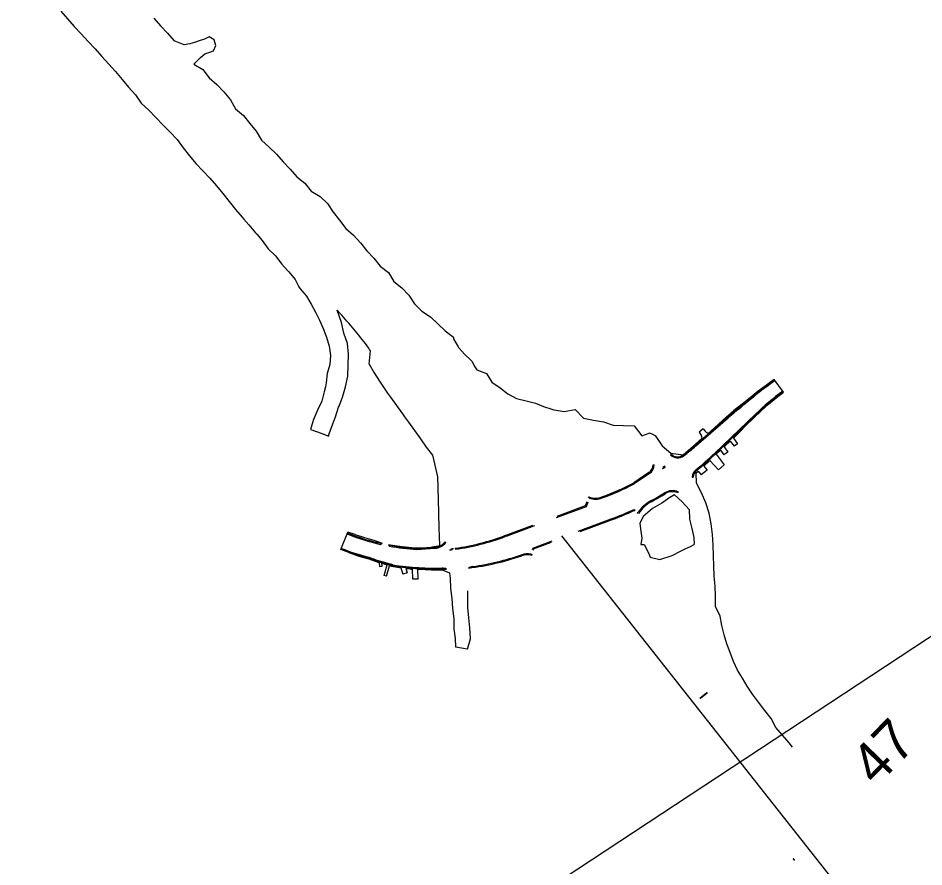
# Model space of a CAD drawing. Extents: x -5665 to 1997148, y 4 to 812485.
# Drawn here: x 1961620 to 1966066, y 802882 to 807051 of the extents above; entities that cross this region are included whole.
import ezdxf

# ---------------------------------------------------------------- set-up
doc = ezdxf.new("R2010")
doc.units = 0
for name, color, linetype in [('RD_EX_H20_TX', 7, 'Continuous'), ('RD_EX_Pavement_Markings', 7, 'Continuous'), ('RD_EX_UT', 7, 'Continuous'), ('RD_PD_CstnLmt', 7, 'Continuous'), ('RD_PD_SW', 7, 'Continuous'), ('RD_SHT_TX', 7, 'Continuous')]:
    doc.layers.add(name, color=color, linetype=linetype)

msp = doc.modelspace()

# ---------------------------------------------------------------- linework, layer by layer
at = {"layer": 'RD_EX_H20_TX'}
msp.add_lwpolyline([(1962404, 800141.4), (1962156.8, 800249.1), (1961619.9, 801061.9), (1967047, 804639.1), (1967746.1, 803578.5), (1967695.1, 802969), (1968000.2, 801689.9), (1968522.9, 801587.9), (1968575.1, 801281.2), (1968568.4, 800839.6), (1968542.7, 800594.7), (1964601.3, 797996.7), (1963740.9, 798826.2)], close=True, dxfattribs=at)
at = {"layer": 'RD_EX_Pavement_Markings'}
msp.add_line((1964286.7, 804508.1), (1966609.3, 801563.1), dxfattribs=at)
at = {"layer": 'RD_EX_UT'}
for p, q in [((1964966.2, 803710.7), (1965000, 803738.1)), ((1965002.4, 803735.3), (1964968.6, 803707.9))]:
    msp.add_line(p, q, dxfattribs=at)
for points in [[(1964999.7, 803735.1), (1965000.2, 803735), (1965000.8, 803735.1), (1965001.1, 803735.6), (1965001.2, 803736.1), (1965001, 803736.6), (1965000.5, 803737), (1965000, 803737), (1964999.5, 803736.7), (1964999.2, 803736.2), (1964999.3, 803735.7), (1964999.6, 803735.2), (1964999.7, 803735.1)], [(1964999.8, 803735.3), (1965000.3, 803735.2), (1965000.7, 803735.4), (1965001, 803735.8), (1965001, 803736.3), (1965000.6, 803736.7), (1965000.2, 803736.8), (1964999.7, 803736.6), (1964999.4, 803736.2), (1964999.5, 803735.7), (1964999.8, 803735.3)], [(1964999.9, 803735.5), (1965000.3, 803735.4), (1965000.7, 803735.6), (1965000.8, 803736), (1965000.6, 803736.4), (1965000.3, 803736.6), (1964999.8, 803736.5), (1964999.6, 803736.1), (1964999.7, 803735.7), (1964999.9, 803735.5)], [(1965000, 803735.7), (1965000.3, 803735.6), (1965000.6, 803735.9), (1965000.6, 803736.2), (1965000.3, 803736.4), (1964999.9, 803736.3), (1964999.8, 803736), (1965000, 803735.7), (1965000, 803735.7)], [(1965000.1, 803735.8), (1965000.3, 803735.8), (1965000.4, 803736.1), (1965000.2, 803736.2), (1965000, 803736), (1965000.1, 803735.8)], [(1965425.1, 802919.4), (1965425.7, 802919.2), (1965426.2, 802919.4), (1965426.6, 802919.8), (1965426.7, 802920.3), (1965426.5, 802920.8), (1965426.1, 802921.2), (1965425.5, 802921.2), (1965425, 802921), (1965424.7, 802920.5), (1965424.7, 802919.9), (1965425.1, 802919.5), (1965425.1, 802919.4)], [(1965425.1, 802919.4), (1965425.7, 802919.2), (1965426.2, 802919.4), (1965426.6, 802919.8), (1965426.7, 802920.3), (1965426.5, 802920.8), (1965426.1, 802921.2), (1965425.5, 802921.2), (1965425, 802921), (1965424.7, 802920.5), (1965424.7, 802919.9), (1965425.1, 802919.5), (1965425.1, 802919.4)], [(1965425.3, 802919.6), (1965425.7, 802919.4), (1965426.2, 802919.6), (1965426.5, 802920), (1965426.5, 802920.5), (1965426.2, 802920.9), (1965425.7, 802921), (1965425.2, 802920.9), (1965424.9, 802920.5), (1965424.9, 802920), (1965425.3, 802919.6)], [(1965425.3, 802919.6), (1965425.7, 802919.4), (1965426.2, 802919.6), (1965426.5, 802920), (1965426.5, 802920.5), (1965426.2, 802920.9), (1965425.7, 802921), (1965425.2, 802920.9), (1965424.9, 802920.5), (1965424.9, 802920), (1965425.3, 802919.6)], [(1965425.4, 802919.7), (1965425.8, 802919.6), (1965426.2, 802919.8), (1965426.3, 802920.2), (1965426.2, 802920.6), (1965425.8, 802920.8), (1965425.3, 802920.7), (1965425.1, 802920.4), (1965425.2, 802919.9), (1965425.4, 802919.7)], [(1965425.4, 802919.7), (1965425.8, 802919.6), (1965426.2, 802919.8), (1965426.3, 802920.2), (1965426.2, 802920.6), (1965425.8, 802920.8), (1965425.3, 802920.7), (1965425.1, 802920.4), (1965425.2, 802919.9), (1965425.4, 802919.7)], [(1965425.5, 802919.9), (1965425.8, 802919.8), (1965426.1, 802920.1), (1965426.1, 802920.4), (1965425.8, 802920.6), (1965425.4, 802920.5), (1965425.3, 802920.2), (1965425.5, 802919.9), (1965425.5, 802919.9)], [(1965425.5, 802919.9), (1965425.8, 802919.8), (1965426.1, 802920.1), (1965426.1, 802920.4), (1965425.8, 802920.6), (1965425.4, 802920.5), (1965425.3, 802920.2), (1965425.5, 802919.9), (1965425.5, 802919.9)], [(1965425.6, 802920.1), (1965425.8, 802920.1), (1965425.9, 802920.3), (1965425.7, 802920.4), (1965425.5, 802920.3), (1965425.6, 802920.1)], [(1965425.6, 802920.1), (1965425.8, 802920.1), (1965425.9, 802920.3), (1965425.7, 802920.4), (1965425.5, 802920.3), (1965425.6, 802920.1)], [(1965428.3, 802915.6), (1965428.8, 802915.4), (1965429.4, 802915.6), (1965429.8, 802916), (1965429.9, 802916.5), (1965429.7, 802917), (1965429.2, 802917.4), (1965428.7, 802917.4), (1965428.2, 802917.2), (1965427.9, 802916.7), (1965427.9, 802916.1), (1965428.2, 802915.6), (1965428.3, 802915.6)], [(1965428.3, 802915.6), (1965428.8, 802915.4), (1965429.4, 802915.6), (1965429.8, 802916), (1965429.9, 802916.5), (1965429.7, 802917), (1965429.2, 802917.4), (1965428.7, 802917.4), (1965428.2, 802917.2), (1965427.9, 802916.7), (1965427.9, 802916.1), (1965428.2, 802915.6), (1965428.3, 802915.6)], [(1965428.4, 802915.8), (1965428.9, 802915.6), (1965429.4, 802915.8), (1965429.6, 802916.2), (1965429.6, 802916.7), (1965429.3, 802917.1), (1965428.8, 802917.2), (1965428.4, 802917.1), (1965428.1, 802916.6), (1965428.1, 802916.1), (1965428.4, 802915.8)], [(1965428.4, 802915.8), (1965428.9, 802915.6), (1965429.4, 802915.8), (1965429.6, 802916.2), (1965429.6, 802916.7), (1965429.3, 802917.1), (1965428.8, 802917.2), (1965428.4, 802917.1), (1965428.1, 802916.6), (1965428.1, 802916.1), (1965428.4, 802915.8)], [(1965428.5, 802915.9), (1965429, 802915.8), (1965429.3, 802916), (1965429.5, 802916.4), (1965429.3, 802916.8), (1965428.9, 802917), (1965428.5, 802916.9), (1965428.3, 802916.6), (1965428.3, 802916.1), (1965428.5, 802915.9)], [(1965428.5, 802915.9), (1965429, 802915.8), (1965429.3, 802916), (1965429.5, 802916.4), (1965429.3, 802916.8), (1965428.9, 802917), (1965428.5, 802916.9), (1965428.3, 802916.6), (1965428.3, 802916.1), (1965428.5, 802915.9)], [(1965428.6, 802916.1), (1965429, 802916), (1965429.2, 802916.3), (1965429.2, 802916.6), (1965428.9, 802916.8), (1965428.6, 802916.7), (1965428.5, 802916.4), (1965428.6, 802916.1), (1965428.6, 802916.1)], [(1965428.6, 802916.1), (1965429, 802916), (1965429.2, 802916.3), (1965429.2, 802916.6), (1965428.9, 802916.8), (1965428.6, 802916.7), (1965428.5, 802916.4), (1965428.6, 802916.1), (1965428.6, 802916.1)], [(1965428.8, 802916.3), (1965429, 802916.3), (1965429.1, 802916.5), (1965428.9, 802916.6), (1965428.7, 802916.5), (1965428.8, 802916.3)], [(1965428.8, 802916.3), (1965429, 802916.3), (1965429.1, 802916.5), (1965428.9, 802916.6), (1965428.7, 802916.5), (1965428.8, 802916.3)]]:
    msp.add_lwpolyline(points, dxfattribs=at)
at = {"layer": 'RD_PD_CstnLmt'}
for p, q in [((1963199.4, 805601.5), (1963186.1, 805616.2)), ((1963342.6, 805350.3), (1963349.6, 805416.2)), ((1965095.2, 805090.2), (1965133, 805123.9)), ((1965058.2, 805056.4), (1965095.2, 805090.2)), ((1964981.6, 805033.9), (1964962.9, 805017)), ((1964962.9, 805017), (1964973.4, 804999.3)), ((1964981.6, 805033.9), (1964991.7, 805021.6)), ((1965007.8, 805012.6), (1965021.1, 805023)), ((1965021.1, 805023), (1965058.2, 805056.4)), ((1964745.4, 805000.5), (1964746.8, 804999.9)), ((1964945.4, 804957.6), (1964976.9, 804987.8)), ((1965115.5, 804972.6), (1965134, 804947.9)), ((1965130.6, 804986.9), (1965150.6, 804960.3)), ((1964883.5, 804906), (1964908.6, 804926)), ((1964908.6, 804926), (1964945.4, 804957.6)), ((1965066.6, 804928.3), (1965083.9, 804905.2)), ((1965085.6, 804945.1), (1965102.8, 804919.3)), ((1965150.6, 804960.3), (1965134, 804947.9)), ((1965045.5, 804908.8), (1965051.3, 804914.8)), ((1965045.5, 804908.8), (1965084.7, 804855.6)), ((1965102.8, 804919.3), (1965083.9, 804905.2)), ((1964984.8, 804849.7), (1965015.7, 804877.6)), ((1964984.8, 804849.7), (1965001.2, 804830.1)), ((1965015.7, 804877.6), (1965057.6, 804831.2)), ((1965057.6, 804831.2), (1965084.7, 804855.6)), ((1964948.5, 804817), (1964957.6, 804825.2)), ((1964957.6, 804825.2), (1964973.1, 804806.7)), ((1965001.2, 804830.1), (1964973.1, 804806.7)), ((1963204.3, 804440.1), (1963238.4, 804526)), ((1963274.8, 804513.8), (1963238.4, 804526)), ((1963274.8, 804513.8), (1963320.2, 804499.7)), ((1963320.2, 804499.7), (1963365.9, 804486.4)), ((1963365.9, 804486.4), (1963406.6, 804472.3)), ((1963243.2, 804425.4), (1963204.3, 804440.1)), ((1963437.9, 804465.4), (1963458, 804461.4)), ((1963458, 804461.4), (1963505.2, 804454.5)), ((1963505.2, 804454.5), (1963552.8, 804449.8)), ((1963552.8, 804449.8), (1963600.5, 804449.4)), ((1963600.5, 804449.4), (1963648.1, 804452.4)), ((1963682.7, 804456.3), (1963648.1, 804452.4)), ((1963243.2, 804425.4), (1963292.1, 804408.5)), ((1963292.1, 804408.5), (1963341.8, 804394.5)), ((1963341.8, 804394.5), (1963390.9, 804376.8)), ((1963390.9, 804376.8), (1963391.9, 804376.5)), ((1963404.9, 804356.5), (1963392.9, 804355.7)), ((1963403.4, 804372.9), (1963430.9, 804364.5)), ((1963416.7, 804312.2), (1963430.9, 804364.5)), ((1963428.2, 804309.1), (1963442.5, 804361.1)), ((1963442.5, 804361.1), (1963492.3, 804351.8)), ((1963498.6, 804351), (1963507.7, 804319.3)), ((1963522.4, 804347.8), (1963544.2, 804344.8)), ((1963522.4, 804347.8), (1963528.9, 804325.4)), ((1963428.2, 804309.1), (1963416.7, 804312.2)), ((1963528.9, 804325.4), (1963507.7, 804319.3)), ((1963557.9, 804294.2), (1963555.1, 804344.5)), ((1963583.8, 804295.6), (1963581.2, 804343.8)), ((1963586.5, 804343.7), (1963648.8, 804340.2)), ((1963648.8, 804340.2), (1963701.2, 804340.2)), ((1963701.2, 804340.2), (1963736.9, 804325.2)), ((1963583.8, 804295.6), (1963557.9, 804294.2))]:
    msp.add_line(p, q, dxfattribs=at)
for points in [[(1961829.4, 807084.3), (1961862.1, 807046.5), (1961895.3, 807009.1), (1961930, 806973.1), (1961963.4, 806935.8), (1961997.5, 806899.3), (1962030.4, 806861.6), (1962064.4, 806825), (1962097.9, 806787.9), (1962130.1, 806749.5), (1962162.4, 806711.3), (1962195.9, 806674.2), (1962224.5, 806632.6), (1962261.7, 806598.9), (1962296.2, 806562.7), (1962330.1, 806525.9), (1962365.8, 806490.8), (1962400.7, 806454.9), (1962429.2, 806413.3), (1962460.8, 806374.5), (1962492.9, 806336.5), (1962526.3, 806299.9), (1962560.1, 806263.6), (1962593.7, 806227.1), (1962625.1, 806188.7), (1962655.9, 806149.8), (1962687.2, 806110.7), (1962719.9, 806072.9), (1962728.5, 806062.9), (1962752.3, 806034.7), (1962785, 805996.7), (1962791.4, 805989.3), (1962817.5, 805958.3), (1962846.5, 805916.8), (1962883.3, 805882.7), (1962883.8, 805882.4), (1962915, 805842.7), (1962942.8, 805810.7), (1962945.4, 805807.7), (1962948.1, 805804.8), (1962980.4, 805766.5), (1962997.6, 805730), (1963003.8, 805720.3), (1963015.1, 805708.1), (1963015.1, 805708.1), (1963027.7, 805694.7), (1963034.7, 805685.1), (1963057.5, 805645.9), (1963078.9, 805606.5), (1963099.1, 805566.7), (1963117.6, 805525.7), (1963133.2, 805483.2), (1963146.1, 805439.4), (1963153.1, 805394.2), (1963150.5, 805348.4), (1963137, 805304.2), (1963131.9, 805259.6), (1963128.1, 805240.2), (1963122.5, 805215.6), (1963112.8, 805175.1), (1963111.2, 805169.8), (1963090.1, 805124.3), (1963070.4, 805078.3), (1963058.1, 805041), (1963055.1, 805030.6), (1963066.1, 805026.5), (1963077.4, 805022.4), (1963083, 805020.3), (1963084.9, 805019.6), (1963107.4, 805011.3), (1963118.7, 805007.2), (1963120.6, 805006.5), (1963126.2, 805004.4), (1963137.4, 805000.3), (1963143.6, 804998), (1963147.2, 805008.1), (1963160.2, 805045.2), (1963177, 805092.3), (1963192.8, 805139.7), (1963195.1, 805144.8), (1963211.6, 805188.3), (1963220.4, 805216.8), (1963226.8, 805239.5), (1963237.9, 805292), (1963240, 805345.6), (1963241.8, 805399.2), (1963237.3, 805452.8)], [(1962285.6, 807050.4), (1962318.2, 807013.2), (1962352.5, 806976.8), (1962385.5, 806939.3)], [(1962582.4, 806943.5), (1962557.4, 806958.2), (1962534.1, 806946.4), (1962509.1, 806939.5), (1962484.8, 806930.6), (1962462.2, 806924.7), (1962435.4, 806919.3), (1962385.5, 806939.3)], [(1962514.6, 806857.2), (1962536, 806875), (1962556.6, 806881.7), (1962579.1, 806890.4), (1962590.4, 806916.7), (1962582.4, 806943.5)], [(1962481.8, 806824.1), (1962514.6, 806857.2)], [(1962481.8, 806824.1), (1962527.1, 806797.6), (1962557.4, 806757.6), (1962594.6, 806723.8), (1962630.1, 806688.5), (1962661.7, 806649.7), (1962686.4, 806604.6), (1962725.7, 806572.8), (1962756.4, 806533.1), (1962788.3, 806494.5), (1962814.8, 806451.1), (1962852.1, 806417.4), (1962887.5, 806382), (1962921.5, 806345.3), (1962954.8, 806308.2), (1962987.8, 806271), (1963027.2, 806239.7), (1963058.6, 806201), (1963102.6, 806174.2), (1963138.8, 806139.7), (1963167, 806097.4), (1963197.9, 806057.8), (1963228.3, 806017.6), (1963265.9, 805983.9), (1963300.6, 805947.5), (1963332, 805908.1), (1963365.8, 805870.9), (1963397.4, 805832.1), (1963438.2, 805801.6), (1963463.6, 805757.2), (1963502.6, 805725), (1963537.6, 805689.2), (1963565.5, 805647.1), (1963601.1, 805611.9), (1963644, 805583.3), (1963680.4, 805548.8), (1963716.6, 805514.1), (1963756.4, 805482.7), (1963756.1, 805475.1), (1963779.2, 805435.8), (1963781.5, 805433), (1963812.3, 805398.3), (1963813.5, 805396.8), (1963840.9, 805371.8), (1963840.9, 805371.8), (1963846.5, 805364.9), (1963861.2, 805337.6), (1963872.1, 805323), (1963918.3, 805304.3), (1963945.7, 805262.2), (1963985.2, 805235.1), (1964023.1, 805205), (1964065.9, 805182.9), (1964113, 805170.7), (1964159.4, 805158.9), (1964198.4, 805142.3), (1964198.5, 805142.3), (1964203.3, 805140.7), (1964233.9, 805130.9), (1964250, 805126.5), (1964281.4, 805121.6), (1964299.8, 805118.9), (1964354.2, 805128.3), (1964394.2, 805085.1), (1964443.5, 805075.6), (1964493.1, 805067.7), (1964540.7, 805052), (1964591.8, 805049.3), (1964643.3, 805048), (1964681.6, 804998.9), (1964717.2, 805012.3)], [(1963237.3, 805452.8), (1963218.6, 805503.6), (1963206.9, 805555.5), (1963186.1, 805616.2)], [(1963342.6, 805350.3), (1963367.2, 805308.6), (1963392.9, 805267.8), (1963419.6, 805227.6), (1963433.2, 805208.2), (1963448, 805188.3), (1963477, 805147.5), (1963506.5, 805106.9), (1963516.8, 805092.3), (1963535.9, 805066.2), (1963565.5, 805025.7), (1963594.1, 804984.5), (1963623.4, 804943.8)], [(1965130.6, 804986.9), (1965161.1, 805017), (1965194.9, 805053), (1965230.2, 805087.5), (1965266.1, 805121.3), (1965302.9, 805154.1), (1965340.9, 805185.5), (1965376.8, 805212.5), (1965330.5, 805275.6), (1965293.6, 805247.9), (1965252.6, 805218), (1965213.2, 805186.1), (1965174.1, 805153.9), (1965133, 805123.9)], [(1964746.8, 804999.9), (1964781.3, 804949.6), (1964823.6, 804913.3), (1964883.5, 804906)], [(1965085.6, 804945.1), (1965088.8, 804947.9), (1965115.5, 804972.6)], [(1963623.4, 804943.8), (1963654.4, 804904), (1963678.5, 804797.5), (1963681.5, 804688.2), (1963685.3, 804547.2), (1963687.6, 804461.5), (1963682.7, 804456.3)], [(1965051.3, 804914.8), (1965066.6, 804928.3)], [(1965224.5, 803730), (1965197.9, 803769), (1965174.7, 803809.3), (1965150, 803848.5), (1965131.6, 803891), (1965114.1, 803933.9), (1965097.9, 803977.3), (1965084.8, 804021.9), (1965073.5, 804067.1), (1965065.3, 804113.2), (1965043.4, 804160.3), (1965043.1, 804210.4), (1965040.7, 804260.4), (1965036.6, 804310.2), (1965034.2, 804360.1), (1965032.4, 804410.1), (1965031.1, 804461.4), (1965028, 804514), (1965021.9, 804566.7), (1965011.4, 804618.9), (1964995.7, 804670), (1964974.1, 804718.8), (1964950.2, 804766.5), (1964948.5, 804817)], [(1964823.8, 804698.7), (1964839.3, 804710), (1964878.9, 804673.9), (1964912.7, 804637.7), (1964915.3, 804589.1), (1964927.1, 804544.3), (1964935.8, 804498.9), (1964938.5, 804464.6)], [(1964823.8, 804698.7), (1964779.9, 804668.8), (1964734.1, 804641.8)], [(1964734.1, 804641.8), (1964687.6, 804602.8), (1964687.4, 804602.3), (1964671.4, 804568.6), (1964676.6, 804530.7), (1964681.1, 804496.6), (1964675.8, 804465.4), (1964675.8, 804465.4), (1964693, 804464.8), (1964713.2, 804424.9), (1964721.7, 804403.1)], [(1964721.7, 804403.1), (1964770.2, 804392.2), (1964829.7, 804411.5), (1964874.4, 804434), (1964894.5, 804443.8), (1964908.2, 804450), (1964919.6, 804455.4), (1964938.5, 804464.6)], [(1963391.9, 804376.5), (1963392.9, 804355.7)], [(1963403.4, 804372.9), (1963404.9, 804356.5)], [(1963492.3, 804351.8), (1963496, 804351.3), (1963498.6, 804351)], [(1963544.2, 804344.8), (1963548.7, 804344.7), (1963555.1, 804344.5)], [(1963581.2, 804343.8), (1963586.5, 804343.7)], [(1963736.9, 804325.2), (1963740.5, 804299.5), (1963742.5, 804249.6), (1963748.8, 804199.9), (1963752.4, 804150), (1963758.6, 804100.3), (1963758.6, 804050.2), (1963765.3, 804003.7), (1963766.2, 803962.4), (1963766.9, 803962.3), (1963768.3, 803962), (1963795.9, 803957), (1963823.4, 803951.9), (1963824.9, 803951.6), (1963824.9, 803951.6), (1963840.2, 804002.5), (1963836.6, 804055.8), (1963832.4, 804105.6), (1963827.7, 804155.4), (1963826.7, 804205.5), (1963826.4, 804237.5)], [(1965420.7, 803468.9), (1965404.9, 803490.3), (1965372.2, 803528.1), (1965339, 803565.6), (1965315.4, 803610.7), (1965284.5, 803650), (1965254.4, 803689.9), (1965224.5, 803730)]]:
    msp.add_lwpolyline(points, dxfattribs=at)
for centre, radius, start, end in [((1961373.6, 803949.9), 2462, 37.2891, 42.1319), ((1961309.9, 804040.1), 2460.5, 34.0056, 34.7351), ((1965011, 805037.4), 25, 219.3511, 262.6705), ((1964597.5, 804688.2), 345.5, 64.6623, 69.7279), ((1964952, 804986.5), 25, 3.0273, 30.8982)]:
    msp.add_arc(centre, radius, start, end, dxfattribs=at)
at = {"layer": 'RD_PD_SW'}
for p, q in [((1965331.3, 805274.5), (1965334.2, 805270.5)), ((1965375.6, 805214.1), (1965372.7, 805218.1)), ((1965039.5, 804914.4), (1965238.8, 805105.6)), ((1964944.7, 804954.5), (1965102.3, 805090.4)), ((1964946.7, 804949.6), (1965105.6, 805086.7)), ((1965043, 804910.8), (1965242.2, 805102)), ((1964822.5, 804905.1), (1964826.1, 804908.6)), ((1964736.5, 804855.8), (1964741.5, 804855.8)), ((1964788.2, 804841.8), (1964790.9, 804838)), ((1964792.4, 804844.7), (1964794.8, 804841.2)), ((1964715.7, 804818.3), (1964641.3, 804767.3)), ((1964718.6, 804814.2), (1964643.9, 804763)), ((1964928.4, 804796.3), (1964933.4, 804796.1)), ((1964860.2, 804723.6), (1964858.2, 804719)), ((1964405.2, 804656.1), (1964412.9, 804677)), ((1964409.1, 804652.2), (1964417.6, 804675.4)), ((1964420.8, 804698.6), (1964418.4, 804692)), ((1964423.8, 804692.3), (1964423.1, 804690.4)), ((1964263.1, 804598), (1964409.1, 804652.2)), ((1964266.3, 804604.5), (1964405.2, 804656.1)), ((1964642.1, 804631.8), (1964645.4, 804629.6)), ((1964642.5, 804637.5), (1964648.2, 804633.8)), ((1964664.7, 804617.1), (1964658.8, 804620.9)), ((1964663.3, 804624), (1964661.6, 804625.1)), ((1964368.3, 804530.4), (1964531.1, 804590.9)), ((1964377.9, 804528.6), (1964532.8, 804586.2)), ((1964023.4, 804514.2), (1964145.6, 804559.6)), ((1964025.1, 804509.5), (1964156, 804558.2)), ((1963236.5, 804521.3), (1963234.7, 804516.6)), ((1964146.1, 804447.8), (1964240.3, 804482.8)), ((1963206.6, 804446), (1963204.8, 804441.4)), ((1963575.3, 804445.7), (1963665.4, 804451.4)), ((1963575.4, 804440.6), (1963665.7, 804446.4)), ((1963715.2, 804478.1), (1963719.1, 804475.1)), ((1963753.5, 804447), (1963753.9, 804442)), ((1963765.6, 804446.8), (1963765.9, 804441.8)), ((1964146.1, 804447.8), (1964143.5, 804438.5)), ((1964150.2, 804444), (1964148.3, 804437.3)), ((1964150.2, 804444), (1964238.3, 804476.7)), ((1964137.5, 804417.3), (1964138.1, 804419.2)), ((1964141, 804411.2), (1964142.9, 804418))]:
    msp.add_line(p, q, dxfattribs=at)
for centre, radius, start, end in [((1967047.5, 802933.9), 2902.4, 126.2503, 130.4535), ((1967047.5, 802933.9), 2897.4, 126.2503, 130.4551), ((1966156.8, 804148.8), 1326, 126.2503, 133.812), ((1966156.8, 804148.8), 1321, 126.2503, 133.812), ((1966999.3, 802891.6), 2904, 129.188, 130.7851), ((1966999.3, 802891.6), 2899, 129.1864, 130.7851), ((1964037.9, 806004.3), 1387.3, 307.543, 310.8192), ((1964037.9, 806004.3), 1392.3, 307.543, 310.751), ((1964857, 804938.5), 48, 223.9559, 307.543), ((1964857, 804938.5), 43, 223.9559, 307.543), ((1964013.2, 805984.2), 1482.4, 308.9999, 313.812), ((1964013.2, 805984.2), 1487.4, 308.9999, 313.812), ((1964688.6, 804857.9), 48, 304.4417, 357.4456), ((1964688.6, 804857.9), 53, 304.4417, 357.7496), ((1964013.2, 805984.2), 1380.4, 303.851, 304.1545), ((1964013.2, 805984.2), 1375.4, 304.1271, 304.5601), ((1964013.2, 805984.2), 1380.4, 304.362, 304.5961), ((1964976.4, 804794.8), 48, 128.9999, 178.2847), ((1964976.4, 804794.8), 43, 128.9999, 178.2847), ((1964013.2, 805984.2), 1369.4, 290.1469, 297.2985), ((1964013.2, 805984.2), 1374.4, 290.1469, 297.3115), ((1964013.2, 805984.2), 1486.4, 298.5815, 301.6403), ((1964013.2, 805984.2), 1491.4, 298.5815, 301.6403), ((1964831.3, 804656.6), 73, 66.7023, 121.6403), ((1964831.3, 804656.6), 68, 66.7023, 121.6403), ((1964452.9, 804785.9), 93, 249.8307, 290.1469), ((1964452.9, 804785.9), 98, 252.7523, 290.1469), ((1964809.7, 804522.7), 178, 118.5884, 145.3211), ((1964809.7, 804522.7), 173, 118.5884, 146.9307), ((1964013.2, 805984.2), 1486.4, 290.3874, 295.0451), ((1964013.2, 805984.2), 1491.4, 290.3874, 294.9383), ((1963642, 805540.6), 1101.9, 248.3103, 257.2657), ((1963642, 805540.6), 1096.9, 248.3103, 257.5395), ((1963616.7, 805536.3), 1099.6, 277.7805, 290.8813), ((1963616.7, 805536.3), 1104.6, 277.7639, 290.873), ((1963642, 805540.6), 1094.9, 289.5662, 290.3874), ((1963642, 805540.6), 1099.9, 289.5662, 290.3874), ((1963642, 805540.6), 1182.9, 248.3103, 255.03), ((1963642, 805540.6), 1177.9, 248.3103, 255.0414), ((1963394.7, 804480.1), 15, 286.9953, 314.9755), ((1963452, 804468.4), 15, 202.1143, 230.2794), ((1963642, 805540.6), 1096.9, 259.2915, 266.519), ((1963642, 805540.6), 1101.9, 259.5687, 266.5353), ((1963661.1, 804519.3), 68, 273.6667, 322.7034), ((1963661.1, 804519.3), 73, 273.6667, 322.7034), ((1963616.7, 805536.3), 1104.6, 276.2624, 277.0365), ((1963616.7, 805536.3), 1099.6, 276.6562, 277.0498), ((1963676, 805613), 1273, 276.9904, 289.0548), ((1963676, 805613), 1268, 277.9346, 289.0548), ((1964118.7, 804331.3), 88, 77.6265, 109.0548), ((1964118.7, 804331.3), 83, 74.3693, 109.0548), ((1963642, 805540.6), 1194.9, 261.1294, 267.3534), ((1963642, 805540.6), 1189.9, 261.1409, 267.3534), ((1963674.5, 805543.9), 1195.2, 265.8014, 271.2604), ((1963701.9, 804301), 48, 65.3719, 91.2604), ((1963857.6, 804309.6), 48, 97.9346, 123.8508), ((1963674.5, 805543.9), 1200.2, 265.8079, 272.2609)]:
    msp.add_arc(centre, radius, start, end, dxfattribs=at)
for points in [[(1963457.7, 804359.9), (1963455.9, 804360.4), (1963454.4, 804360.8), (1963452.4, 804361.3), (1963451.8, 804361.4), (1963450.5, 804361.8), (1963448.6, 804362.3), (1963446.7, 804362.8), (1963444.1, 804363.4), (1963442.9, 804363.8), (1963439.1, 804364.8), (1963436.5, 804365.5), (1963431.4, 804366.9), (1963428.9, 804367.6), (1963416.2, 804371.2), (1963406.1, 804374.2), (1963386, 804380.5), (1963376, 804383.8), (1963363.5, 804388.1), (1963361, 804388.9), (1963356, 804390.7), (1963353.5, 804391.5), (1963349.8, 804392.9), (1963348.6, 804393.3), (1963346.1, 804394.2), (1963344.9, 804394.7), (1963342.4, 804395.6), (1963341.1, 804396), (1963338.7, 804396.9), (1963337.5, 804397.3), (1963336.4, 804397.8)], [(1963458.7, 804364.8), (1963457.3, 804365.2), (1963455.9, 804365.5), (1963454, 804366), (1963453.4, 804366.2), (1963452.1, 804366.5), (1963451.4, 804366.7), (1963449.5, 804367.2), (1963448.2, 804367.5), (1963445.7, 804368.2), (1963444.4, 804368.5), (1963440.6, 804369.6), (1963438.1, 804370.3), (1963433, 804371.7), (1963430.4, 804372.4), (1963417.8, 804376), (1963407.6, 804379), (1963387.5, 804385.3), (1963377.5, 804388.6), (1963365, 804392.8), (1963362.5, 804393.7), (1963357.5, 804395.4), (1963355.1, 804396.3), (1963351.3, 804397.6), (1963350.1, 804398.1), (1963347.6, 804399), (1963346.4, 804399.4), (1963343.9, 804400.3), (1963342.7, 804400.8), (1963340.2, 804401.7), (1963339.1, 804402.1), (1963337.9, 804402.5)]]:
    msp.add_open_spline(points, degree=3, dxfattribs=at)

# ---------------------------------------------------------------- texts
at = {"layer": 'RD_SHT_TX'}
msp.add_text('47', height=200, rotation=45.6376, dxfattribs=at).set_placement((1965832, 803272.4))

doc.saveas('drawing.dxf')
